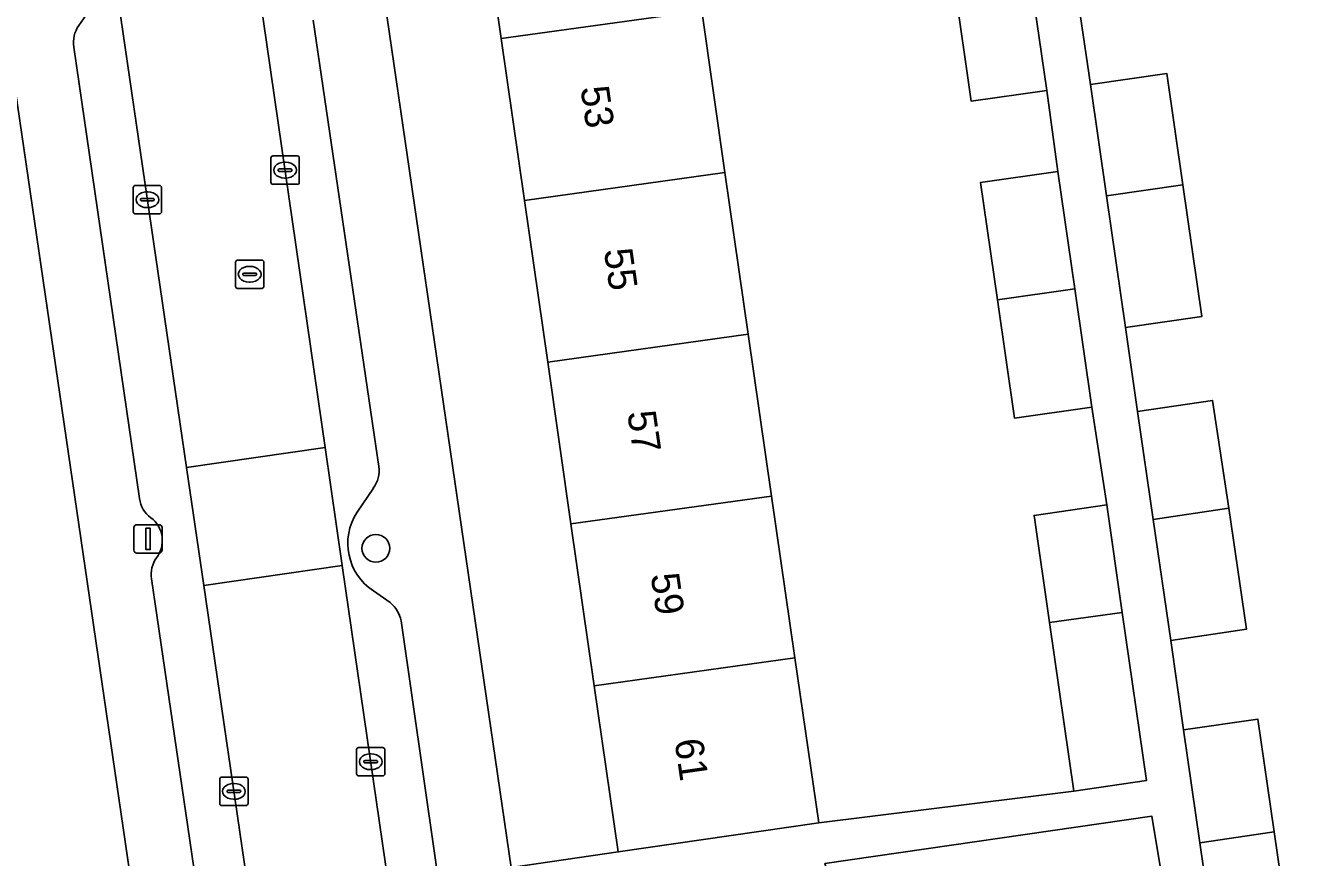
# Model space of a CAD drawing. Extents: x 159053 to 160042, y 380449 to 381423.
# Drawn here: x 159509.07 to 159553.7, y 381023.14 to 381052.46 of the extents above; entities that cross this region are included whole.
import ezdxf

# ---------------------------------------------------------------- set-up
doc = ezdxf.new("R2010")
doc.units = 0
for name, color, linetype in [('IMGEO_Boom', 7, 'Continuous'), ('IMGEO_Erf', 7, 'Continuous'), ('IMGEO_Kolk', 7, 'Continuous'), ('IMGEO_Lichtmast', 7, 'Continuous'), ('IMGEO_Pand', 7, 'Continuous'), ('IMGEO_Pand_nummerreeks', 7, 'Continuous'), ('IMGEO_Parkeervlak_open', 7, 'Continuous'), ('IMGEO_Rijbaan_lokaal_open', 7, 'Continuous'), ('IMGEO_Rioolput', 7, 'Continuous'), ('IMGEO_Voetpad_open', 7, 'Continuous')]:
    doc.layers.add(name, color=color, linetype=linetype)

msp = doc.modelspace()

# ---------------------------------------------------------------- linework, layer by layer
at = {"layer": 'IMGEO_Boom'}
msp.add_circle((159521.415, 381034.038), 0.489, dxfattribs=at)
at = {"layer": 'IMGEO_Erf'}
msp.add_lwpolyline([(159523.361, 381069.092), (159522.54, 381074.791), (159521.719, 381080.49), (159520.898, 381086.189), (159520.077, 381091.888), (159519.256, 381097.587), (159518.435, 381103.287), (159517.592, 381109.137), (159513.655, 381108.522), (159513.71, 381108.241), (159526.177, 381022.796), (159529.951, 381023.347), (159529.108, 381029.197), (159528.287, 381034.896), (159527.466, 381040.595), (159526.645, 381046.294), (159525.824, 381051.994), (159525.003, 381057.693), (159524.182, 381063.392)], close=True, dxfattribs=at)
for points in [[(159500.763, 381003.012), (159515.381, 381005.067), (159512.894, 381021.627), (159505.664, 381071.035)], [(159532.89, 381052.975), (159533.711, 381047.275), (159534.532, 381041.576), (159535.353, 381035.877), (159536.174, 381030.178), (159537.011, 381024.365), (159545.995, 381025.487), (159545.141, 381031.423), (159544.597, 381035.199), (159547.155, 381035.568), (159546.636, 381039.015), (159543.908, 381038.621), (159543.305, 381042.794), (159542.709, 381046.922), (159545.437, 381047.316), (159545.043, 381050.169), (159542.386, 381049.785), (159541.781, 381053.982)], [(159546.225, 381052.845), (159546.581, 381050.377), (159549.271, 381050.765), (159549.837, 381046.845), (159550.507, 381042.208), (159547.816, 381041.82), (159548.245, 381038.855), (159550.887, 381039.245), (159551.461, 381035.45), (159552.077, 381031.189), (159549.408, 381030.795), (159549.864, 381027.64), (159552.483, 381028.019), (159553.056, 381024.051), (159553.699, 381019.598), (159551.079, 381019.219), (159551.563, 381015.872), (159554.264, 381016.262)], [(159556.975, 381008.526), (159553.35, 381008.042), (159553.218, 381009.034), (159552.403, 381008.925), (159553.047, 381004.101), (159551.614, 381003.909), (159551.348, 381005.893), (159548.742, 381005.544), (159548.175, 381009.778), (159547.598, 381014.08), (159550.203, 381014.43), (159549.227, 381021.703), (159548.75, 381024.601), (159537.231, 381022.938), (159540.192, 381013.416), (159541.927, 381007.834), (159544.034, 381008.49), (159545.77, 381002.909), (159543.663, 381002.253), (159544.363, 381000)]]:
    msp.add_lwpolyline(points, dxfattribs=at)
at = {"layer": 'IMGEO_Kolk'}
for p, q in [((159517.717, 381046.933), (159517.717, 381047.785)), ((159517.792, 381047.859), (159518.644, 381047.859)), ((159518.205, 381047.639), (159518.23, 381047.639)), ((159518.718, 381047.785), (159518.718, 381046.933)), ((159517.976, 381047.353), (159517.976, 381047.365)), ((159518.414, 381047.316), (159518.016, 381047.316)), ((159518.019, 381047.402), (159518.417, 381047.402)), ((159518.46, 381047.365), (159518.46, 381047.353)), ((159512.868, 381045.892), (159512.868, 381046.744)), ((159512.943, 381046.818), (159513.795, 381046.818)), ((159513.869, 381046.744), (159513.869, 381045.892)), ((159518.644, 381046.859), (159517.792, 381046.859)), ((159518.228, 381047.079), (159518.203, 381047.079)), ((159513.127, 381046.312), (159513.127, 381046.324)), ((159513.565, 381046.275), (159513.167, 381046.275)), ((159513.17, 381046.361), (159513.568, 381046.361)), ((159513.356, 381046.598), (159513.381, 381046.598)), ((159513.611, 381046.324), (159513.611, 381046.312)), ((159513.795, 381045.818), (159512.943, 381045.818)), ((159513.379, 381046.038), (159513.354, 381046.038)), ((159520.734, 381026.096), (159520.734, 381026.948)), ((159520.809, 381027.022), (159521.661, 381027.022)), ((159521.222, 381026.802), (159521.247, 381026.802)), ((159521.735, 381026.948), (159521.735, 381026.096)), ((159520.993, 381026.516), (159520.993, 381026.528)), ((159521.431, 381026.479), (159521.033, 381026.479)), ((159521.036, 381026.565), (159521.434, 381026.565)), ((159521.245, 381026.242), (159521.22, 381026.242)), ((159521.477, 381026.528), (159521.477, 381026.516)), ((159515.914, 381025.052), (159515.914, 381025.904)), ((159515.989, 381025.978), (159516.841, 381025.978)), ((159516.402, 381025.758), (159516.427, 381025.758)), ((159516.915, 381025.904), (159516.915, 381025.052)), ((159521.661, 381026.022), (159520.809, 381026.022)), ((159516.173, 381025.472), (159516.173, 381025.484)), ((159516.611, 381025.435), (159516.213, 381025.435)), ((159516.216, 381025.521), (159516.614, 381025.521)), ((159516.657, 381025.484), (159516.657, 381025.472)), ((159516.841, 381024.978), (159515.989, 381024.978)), ((159516.425, 381025.198), (159516.4, 381025.198))]:
    msp.add_line(p, q, dxfattribs=at)
for points in [[(159517.717, 381046.933), (159517.717, 381047.785)], [(159517.792, 381047.859), (159518.644, 381047.859)], [(159518.718, 381047.785), (159518.718, 381046.933)], [(159512.868, 381045.892), (159512.868, 381046.744)], [(159512.943, 381046.818), (159513.795, 381046.818)], [(159513.869, 381046.744), (159513.869, 381045.892)], [(159518.644, 381046.859), (159517.792, 381046.859)], [(159513.795, 381045.818), (159512.943, 381045.818)], [(159520.734, 381026.096), (159520.734, 381026.948)], [(159520.809, 381027.022), (159521.661, 381027.022)], [(159521.735, 381026.948), (159521.735, 381026.096)], [(159515.914, 381025.052), (159515.914, 381025.904)], [(159515.989, 381025.978), (159516.841, 381025.978)], [(159516.915, 381025.904), (159516.915, 381025.052)], [(159521.661, 381026.022), (159520.809, 381026.022)], [(159516.841, 381024.978), (159515.989, 381024.978)]]:
    msp.add_lwpolyline(points, dxfattribs=at)
for centre, radius, start, end in [((159517.794, 381047.783), 0.0765, 91.552, 178.448), ((159517.794, 381047.783), 0.0765, 91.552, 178.448), ((159518.642, 381047.783), 0.0765, 1.552, 88.448), ((159518.642, 381047.783), 0.0765, 1.552, 88.448), ((159518.016, 381047.362), 0.0403, 85.8775, 175.7526), ((159518.013, 381047.352), 0.0366, 178.938, 274.7102), ((159518.417, 381047.359), 0.043, 264.8664, 352.4533), ((159518.421, 381047.364), 0.0386, 1.7309, 96.639), ((159512.945, 381046.742), 0.0765, 91.552, 178.448), ((159512.945, 381046.742), 0.0765, 91.552, 178.448), ((159513.793, 381046.742), 0.0765, 1.552, 88.448), ((159513.793, 381046.742), 0.0765, 1.552, 88.448), ((159517.794, 381046.935), 0.0765, 181.552, 268.448), ((159517.794, 381046.935), 0.0765, 181.552, 268.448), ((159518.642, 381046.935), 0.0765, 271.552, 358.448), ((159518.642, 381046.935), 0.0765, 271.552, 358.448), ((159513.167, 381046.321), 0.0403, 85.8775, 175.7526), ((159513.164, 381046.311), 0.0366, 178.938, 274.7102), ((159513.568, 381046.318), 0.043, 264.8664, 352.4533), ((159513.572, 381046.323), 0.0386, 1.7309, 96.639), ((159512.945, 381045.894), 0.0765, 181.552, 268.448), ((159512.945, 381045.894), 0.0765, 181.552, 268.448), ((159513.793, 381045.894), 0.0765, 271.552, 358.448), ((159513.793, 381045.894), 0.0765, 271.552, 358.448), ((159520.811, 381026.946), 0.0765, 91.552, 178.448), ((159520.811, 381026.946), 0.0765, 91.552, 178.448), ((159521.659, 381026.946), 0.0765, 1.552, 88.448), ((159521.659, 381026.946), 0.0765, 1.552, 88.448), ((159521.033, 381026.525), 0.0403, 85.8775, 175.7526), ((159521.03, 381026.515), 0.0366, 178.938, 274.7102), ((159521.434, 381026.522), 0.043, 264.8664, 352.4533), ((159521.438, 381026.527), 0.0386, 1.7309, 96.639), ((159515.991, 381025.902), 0.0765, 91.552, 178.448), ((159515.991, 381025.902), 0.0765, 91.552, 178.448), ((159516.839, 381025.902), 0.0765, 1.552, 88.448), ((159516.839, 381025.902), 0.0765, 1.552, 88.448), ((159520.811, 381026.098), 0.0765, 181.552, 268.448), ((159520.811, 381026.098), 0.0765, 181.552, 268.448), ((159521.659, 381026.098), 0.0765, 271.552, 358.448), ((159521.659, 381026.098), 0.0765, 271.552, 358.448), ((159516.213, 381025.481), 0.0403, 85.8775, 175.7526), ((159516.21, 381025.471), 0.0366, 178.938, 274.7102), ((159516.614, 381025.478), 0.043, 264.8664, 352.4533), ((159516.618, 381025.483), 0.0386, 1.7309, 96.639), ((159515.991, 381025.054), 0.0765, 181.552, 268.448), ((159515.991, 381025.054), 0.0765, 181.552, 268.448), ((159516.839, 381025.054), 0.0765, 271.552, 358.448), ((159516.839, 381025.054), 0.0765, 271.552, 358.448)]:
    msp.add_arc(centre, radius, start, end, dxfattribs=at)
for centre, major_axis, ratio, start_param, end_param in [((159518.204, 381047.359), (-0.387, 0.002), 0.722429, 4.712389, 7.853982), ((159518.229, 381047.359), (-0.39, 0.002), 0.717154, 1.570796, 4.712389), ((159513.355, 381046.318), (-0.387, 0.002), 0.722429, 4.712389, 7.853982), ((159513.38, 381046.318), (-0.39, 0.002), 0.717154, 1.570796, 4.712389), ((159521.221, 381026.522), (-0.387, 0.002), 0.722429, 4.712389, 7.853982), ((159521.246, 381026.522), (-0.39, 0.002), 0.717154, 1.570796, 4.712389), ((159516.401, 381025.478), (-0.387, 0.002), 0.722429, 4.712389, 7.853982), ((159516.426, 381025.478), (-0.39, 0.002), 0.717154, 1.570796, 4.712389)]:
    msp.add_ellipse(centre, major_axis=major_axis, ratio=ratio, start_param=start_param, end_param=end_param, dxfattribs=at)
at = {"layer": 'IMGEO_Lichtmast'}
for p, q in [((159512.896, 381033.97), (159512.896, 381034.77)), ((159512.896, 381034.77), (159512.896, 381033.97)), ((159512.996, 381034.87), (159513.786, 381034.87)), ((159513.786, 381034.87), (159512.996, 381034.87)), ((159513.886, 381034.77), (159513.886, 381033.97)), ((159513.886, 381033.97), (159513.886, 381034.77)), ((159513.786, 381033.87), (159512.996, 381033.87)), ((159512.996, 381033.87), (159513.786, 381033.87))]:
    msp.add_line(p, q, dxfattribs=at)
msp.add_lwpolyline([(159513.316, 381034.745), (159513.466, 381034.745), (159513.466, 381033.995), (159513.316, 381033.995), (159513.316, 381034.745)], dxfattribs=at)
for centre, start, end in [((159512.996, 381034.77), 90, 180), ((159512.996, 381034.77), 90, 180), ((159513.786, 381034.77), 0, 90), ((159513.786, 381034.77), 360, 90), ((159512.996, 381033.97), 180, 270), ((159512.996, 381033.97), 180, 270), ((159513.786, 381033.97), 270, 0), ((159513.786, 381033.97), 270, 0)]:
    msp.add_arc(centre, 0.1, start, end, dxfattribs=at)
at = {"layer": 'IMGEO_Pand'}
for points in [[(159532.069, 381058.674), (159525.003, 381057.693), (159525.824, 381051.994), (159532.89, 381052.975)], [(159544.437, 381054.366), (159541.781, 381053.982), (159542.386, 381049.785), (159545.043, 381050.169)], [(159533.711, 381047.275), (159532.89, 381052.975), (159525.824, 381051.994), (159526.645, 381046.294)], [(159549.837, 381046.845), (159549.271, 381050.765), (159546.581, 381050.377), (159547.148, 381046.448)], [(159533.711, 381047.275), (159526.645, 381046.294), (159527.466, 381040.595), (159534.532, 381041.576)], [(159546.035, 381043.173), (159545.437, 381047.316), (159542.709, 381046.922), (159543.305, 381042.794)], [(159549.837, 381046.845), (159547.148, 381046.448), (159547.816, 381041.82), (159550.507, 381042.208)], [(159546.035, 381043.173), (159543.305, 381042.794), (159543.908, 381038.621), (159546.636, 381039.015)], [(159527.466, 381040.595), (159528.287, 381034.896), (159535.353, 381035.877), (159534.532, 381041.576)], [(159548.245, 381038.855), (159548.793, 381035.056), (159551.461, 381035.45), (159550.887, 381039.245)], [(159535.353, 381035.877), (159528.287, 381034.896), (159529.108, 381029.197), (159536.174, 381030.178)], [(159547.155, 381035.568), (159544.597, 381035.199), (159545.141, 381031.423), (159547.699, 381031.778)], [(159551.461, 381035.45), (159548.793, 381035.056), (159549.408, 381030.795), (159552.077, 381031.189)], [(159547.699, 381031.778), (159545.141, 381031.423), (159545.995, 381025.487), (159548.554, 381025.856)], [(159536.174, 381030.178), (159529.108, 381029.197), (159529.951, 381023.347), (159534.9, 381024.061), (159537.011, 381024.365)], [(159550.438, 381023.665), (159553.056, 381024.051), (159552.483, 381028.019), (159549.864, 381027.64)], [(159550.438, 381023.665), (159551.079, 381019.219), (159553.699, 381019.598), (159553.056, 381024.051)]]:
    msp.add_lwpolyline(points, close=True, dxfattribs=at)
at = {"layer": 'IMGEO_Parkeervlak_open'}
for points in [[(159511.184, 381095.915), (159519.631, 381037.591), (159520.233, 381033.434), (159522.084, 381020.653)], [(159517.331, 381019.216), (159515.356, 381032.728), (159514.749, 381036.884), (159506.251, 381095.031)], [(159511.523, 381053.278), (159510.952, 381052.459)], [(159521.522, 381036.917), (159519.21, 381052.637)], [(159510.774, 381051.692), (159513.092, 381035.788)], [(159520.751, 381035.309), (159521.326, 381036.157)], [(159513.513, 381032.959), (159515.408, 381020.062)], [(159521.919, 381032.129), (159521.335, 381032.537)], [(159523.884, 381020.517), (159522.303, 381031.481)]]:
    msp.add_lwpolyline(points, dxfattribs=at)
for centre, radius, start, end in [((159511.849, 381051.847), 1.086, 145.6814, 188.1876), ((159520.513, 381036.772), 1.019, 322.8909, 8.1868), ((159514.06, 381035.904), 0.974, 186.8164, 234.2333), ((159512.898, 381034.314), 0.995, 322.3301, 53.4509), ((159522.429, 381034.215), 2.003, 146.903, 236.8909), ((159514.577, 381033.107), 1.074, 146.1236, 187.9432), ((159521.22, 381031.277), 1.102, 10.6618, 50.6395)]:
    msp.add_arc(centre, radius, start, end, dxfattribs=at)
at = {"layer": 'IMGEO_Rijbaan_lokaal_open'}
for points in [[(159514.749, 381036.884), (159519.631, 381037.591), (159511.184, 381095.915), (159506.23, 381095.173), (159506.251, 381095.031)], [(159514.749, 381036.884), (159515.356, 381032.728), (159520.233, 381033.434), (159519.631, 381037.591)]]:
    msp.add_lwpolyline(points, close=True, dxfattribs=at)
msp.add_lwpolyline([(159522.084, 381020.653), (159520.233, 381033.434), (159515.356, 381032.728), (159517.331, 381019.216)], dxfattribs=at)
at = {"layer": 'IMGEO_Rioolput'}
for p, q in [((159516.471, 381043.264), (159516.471, 381044.116)), ((159516.546, 381044.19), (159517.398, 381044.19)), ((159517.472, 381044.116), (159517.472, 381043.264)), ((159516.73, 381043.684), (159516.73, 381043.696)), ((159517.168, 381043.647), (159516.77, 381043.647)), ((159516.773, 381043.733), (159517.171, 381043.733)), ((159516.959, 381043.97), (159516.984, 381043.97)), ((159517.214, 381043.696), (159517.214, 381043.684)), ((159517.398, 381043.19), (159516.546, 381043.19)), ((159516.982, 381043.41), (159516.957, 381043.41))]:
    msp.add_line(p, q, dxfattribs=at)
for points in [[(159516.471, 381043.264), (159516.471, 381044.116)], [(159516.546, 381044.19), (159517.398, 381044.19)], [(159517.472, 381044.116), (159517.472, 381043.264)], [(159517.398, 381043.19), (159516.546, 381043.19)]]:
    msp.add_lwpolyline(points, dxfattribs=at)
for centre, radius, start, end in [((159516.548, 381044.114), 0.0765, 91.552, 178.448), ((159516.548, 381044.114), 0.0765, 91.552, 178.448), ((159517.396, 381044.114), 0.0765, 1.552, 88.448), ((159517.396, 381044.114), 0.0765, 1.552, 88.448), ((159516.77, 381043.693), 0.0403, 85.8775, 175.7526), ((159516.767, 381043.683), 0.0366, 178.938, 274.7102), ((159517.171, 381043.69), 0.043, 264.8664, 352.4533), ((159517.175, 381043.695), 0.0386, 1.7309, 96.639), ((159516.548, 381043.266), 0.0765, 181.552, 268.448), ((159516.548, 381043.266), 0.0765, 181.552, 268.448), ((159517.396, 381043.266), 0.0765, 271.552, 358.448), ((159517.396, 381043.266), 0.0765, 271.552, 358.448)]:
    msp.add_arc(centre, radius, start, end, dxfattribs=at)
for centre, major_axis, ratio, start_param, end_param in [((159516.958, 381043.69), (-0.387, 0.002), 0.722429, 4.712389, 7.853982), ((159516.983, 381043.69), (-0.39, 0.002), 0.717154, 1.570796, 4.712389)]:
    msp.add_ellipse(centre, major_axis=major_axis, ratio=ratio, start_param=start_param, end_param=end_param, dxfattribs=at)
at = {"layer": 'IMGEO_Voetpad_open'}
for points in [[(159495.274, 381170.535), (159491.067, 381170.966), (159492.161, 381163.484), (159497.307, 381128.294), (159497.503, 381126.951), (159500, 381109.876), (159500.255, 381108.132), (159502.714, 381091.198), (159505.448, 381072.514), (159505.664, 381071.035), (159512.894, 381021.627), (159515.381, 381005.067), (159515.537, 381002.185)], [(159536.881, 380989.854), (159536.416, 380989.716), (159536.175, 380990.447), (159531.838, 381003.607), (159526.805, 381019.287), (159526.692, 381019.269), (159526.177, 381022.796), (159513.71, 381108.241), (159513.655, 381108.522), (159513.151, 381111.974), (159505.308, 381165.647), (159502.772, 381165.23), (159505.28, 381148.066)], [(159544.437, 381054.366), (159545.043, 381050.169), (159545.437, 381047.316), (159546.035, 381043.173), (159546.636, 381039.015), (159547.155, 381035.568), (159547.699, 381031.778), (159548.554, 381025.856), (159545.995, 381025.487), (159537.011, 381024.365), (159534.9, 381024.061), (159529.951, 381023.347), (159526.177, 381022.796)], [(159510.952, 381052.459), (159511.523, 381053.278)], [(159519.21, 381052.637), (159521.522, 381036.917)], [(159554.914, 381011.763), (159552.213, 381011.364), (159551.563, 381015.872), (159551.079, 381019.219), (159550.438, 381023.665), (159549.864, 381027.64), (159549.408, 381030.795), (159548.793, 381035.056), (159548.245, 381038.855), (159547.816, 381041.82), (159547.148, 381046.448), (159546.581, 381050.377), (159546.225, 381052.845)], [(159513.092, 381035.788), (159510.774, 381051.692)], [(159521.326, 381036.157), (159520.751, 381035.309)], [(159515.408, 381020.062), (159513.513, 381032.959)], [(159521.335, 381032.537), (159521.919, 381032.129)], [(159522.303, 381031.481), (159523.884, 381020.517)], [(159537.231, 381022.938), (159548.75, 381024.601), (159549.227, 381021.703)]]:
    msp.add_lwpolyline(points, dxfattribs=at)
for centre, radius, start, end in [((159511.849, 381051.847), 1.086, 145.6814, 188.1876), ((159520.513, 381036.772), 1.019, 322.8909, 8.1868), ((159514.06, 381035.904), 0.974, 186.8164, 234.2333), ((159512.898, 381034.314), 0.995, 322.3301, 53.4509), ((159522.429, 381034.215), 2.003, 146.903, 236.8909), ((159514.577, 381033.107), 1.074, 146.1236, 187.9432), ((159521.22, 381031.277), 1.102, 10.6618, 50.6395)]:
    msp.add_arc(centre, radius, start, end, dxfattribs=at)

# ---------------------------------------------------------------- texts
at = {"layer": 'IMGEO_Pand_nummerreeks'}
for s, p in [('53', (159528.62, 381050.262)), ('55', (159529.444, 381044.542)), ('57', (159530.268, 381038.823)), ('59', (159531.091, 381033.104)), ('61', (159531.931, 381027.272))]:
    msp.add_text(s, height=1, rotation=278.1977, dxfattribs=at).set_placement(p)

doc.saveas('drawing.dxf')
